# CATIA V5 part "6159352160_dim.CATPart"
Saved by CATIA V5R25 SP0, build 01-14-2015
Part number: 6159352160_dim
Source: made
Property "PROI_CREATED_ON": "12/17/2008 9:21:37 AM"
Property "BLANK_DRAWING": "--"
Property "DRAWN_BY": "FPA"
Property "FINISH": "--"
Property "HEAT_TREATMENT": "ASSIGN"
Property "MATERIAL": "ASSIGN"
Property "PROJECT": "--"
Property "PROTOTYPE_NO": "--"
Property "RELATED_DRAWING": "--"
Property "COMPLETE_MATERIAL": "ASSIGN-ASSIGN"
Property "DESCRIPTION": "Q-SHIELD 900-S"
Property "DRAWING_EXIST": "--"
Property "MANUFACTURER": "--"
Property "MANUFACTURER_2": "--"
Property "MANUFACTURER_REF": "--"
Property "TYPE_PART": "--"
Property "TODAY_DATE": "2021/06/10"
Property "PDMREV": "01.0"
Property "PDMRL": "Production"
Property "PROI_REVISION": "01"
Property "PROI_VERSION": "0"
Property "PROI_RELEASE": "Production"
Property "PTC_MODIFIED": false
Property "MFG_WP_MATERIAL": "ASSIGN"
Property "COMPANY_CODE": "---"
Property "DESCRIPTION_JP": "--"
Property "PQP_DOCUMENT": "--"
Property "GHOST": false
Property "NO_PART": false
Property "PTC_WM_ITERATION": "0"
Property "PTC_WM_VERSION": "01.0"
Property "PTC_WM_CREATED_ON": "10-Jun-21 03:15:09 PM"
Property "PTC_WM_MODIFIED_ON": "10-Jun-21 03:21:17 PM"
Property "PTC_WM_NAME": "6159352160_dim.prt"
Property "PTC_WM_NUMBER": "6159352160_DIM.PRT"
Property "PTC_WM_LIFECYCLE_STATE": "Production"
Property "PTC_WM_LIFECYCLE": "Design_Process"
Property "PTC_WM_REVISION": "01"
Property "PTC_WM_CREATED_BY": "Florian Pavageau (Grefpav) (Grefpav: CPD)"
Property "PTC_WM_MODIFIED_BY": "Florian Pavageau (Grefpav) (Grefpav: CPD)"
Property "PTC_ORGANIZATION_ID": "CPD"
Property "PTC_WM_LOCATION": "/Products/TORQUE MEASUREMENT SYSTEMS/A2010 - DELTAWRENCH GEN2/9-01-Dimensional D"
Property "PTC_WM_PART_NAME": "6159352160_dim.prt"
Property "PTC_WM_PART_NUMBER": "6159352160_DIM"
Property "PTC_WM_TEAM": "Default"
Property "EXPORT_CONTROL": "NULL"
Property "PTC_COMMON_NAME": "6159352160_dim.prt"
Property "PTC_MASTER_MATERIAL": "ASSIGN"
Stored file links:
  d:\ptc\Echange\temp\6159352160_dim.CATPart

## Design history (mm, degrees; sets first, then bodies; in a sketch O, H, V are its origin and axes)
AxisSystem1 "CS0": origin (0, 0, 0), X (1, 0, 0), Y (0, 1, 0), Z (0, 0, 1)
Set1
  DatumSurface1 "Sheet.1"
  DatumSurface2 "Sheet.2"
  DatumSurface3 "Sheet.3"
  DatumSurface4 "Sheet.4"
  DatumSurface5 "Sheet.5"
  DatumSurface6 "Sheet.6"
  DatumSurface7 "Sheet.7"
  DatumSurface8 "Sheet.8"
  DatumSurface9 "Sheet.9"
  Plane1 "RIGHT": stored without definition
  Plane2 "TOP": stored without definition
  Plane3 "FRONT": stored without definition
Body1 "PartBody" (main body)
